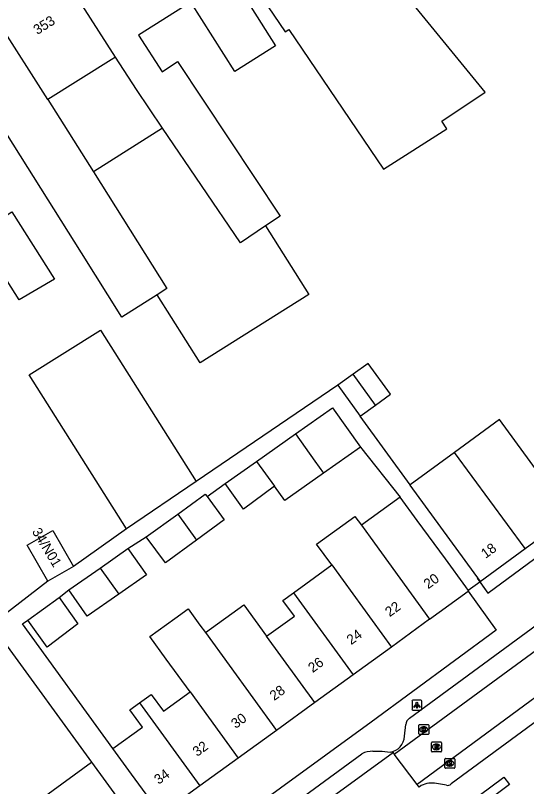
# Model space of a CAD drawing. Extents: x 159822 to 160765, y 380693 to 381634.
# Drawn here: x 160009.6 to 160061, y 381446.3 to 381523.9 of the extents above; entities that cross this region are included whole.
import ezdxf

# ---------------------------------------------------------------- set-up
doc = ezdxf.new("R2010")
doc.units = 0
for name, color, linetype in [('IMGEO_Kolk', 7, 'Continuous'), ('IMGEO_Lichtpunt', 7, 'Continuous'), ('IMGEO_Muur', 7, 'Continuous'), ('IMGEO_Pand', 7, 'Continuous'), ('IMGEO_Pand_nummerreeks', 7, 'Continuous'), ('IMGEO_Parkeervlak_open', 7, 'Continuous'), ('IMGEO_Rijbaan_lokaal_open', 7, 'Continuous'), ('IMGEO_Rioolput', 7, 'Continuous'), ('IMGEO_Voetpad_open', 7, 'Continuous')]:
    doc.layers.add(name, color=color, linetype=linetype)

msp = doc.modelspace()

# ---------------------------------------------------------------- linework, layer by layer
at = {"layer": 'IMGEO_Kolk'}
for p, q in [((160050.192, 381451.574), (160050.192, 381452.426)), ((160050.267, 381452.5), (160051.119, 381452.5)), ((160050.68, 381452.28), (160050.705, 381452.28)), ((160051.193, 381452.426), (160051.193, 381451.574)), ((160051.119, 381451.5), (160050.267, 381451.5)), ((160050.703, 381451.72), (160050.678, 381451.72)), ((160052.803, 381448.172), (160052.803, 381449.024)), ((160052.878, 381449.098), (160053.73, 381449.098)), ((160053.804, 381449.024), (160053.804, 381448.172)), ((160053.314, 381448.318), (160053.289, 381448.318)), ((160053.291, 381448.878), (160053.316, 381448.878)), ((160053.73, 381448.098), (160052.878, 381448.098))]:
    msp.add_line(p, q, dxfattribs=at)
for points in [[(160050.192, 381451.574), (160050.192, 381452.426)], [(160050.267, 381452.5), (160051.119, 381452.5)], [(160050.513, 381452.2), (160050.636, 381452.2), (160050.636, 381452.049), (160050.766, 381452.2), (160050.93, 381452.2), (160050.784, 381452.049), (160050.937, 381451.8), (160050.785, 381451.8), (160050.7, 381451.964), (160050.636, 381451.897), (160050.636, 381451.8), (160050.513, 381451.8), (160050.513, 381452.2)], [(160051.193, 381452.426), (160051.193, 381451.574)], [(160051.119, 381451.5), (160050.267, 381451.5)], [(160052.803, 381448.172), (160052.803, 381449.024)], [(160052.878, 381449.098), (160053.73, 381449.098)], [(160053.804, 381449.024), (160053.804, 381448.172)], [(160053.124, 381448.798), (160053.247, 381448.798), (160053.247, 381448.647), (160053.377, 381448.798), (160053.541, 381448.798), (160053.395, 381448.647), (160053.548, 381448.398), (160053.396, 381448.398), (160053.311, 381448.562), (160053.247, 381448.495), (160053.247, 381448.398), (160053.124, 381448.398), (160053.124, 381448.798)], [(160053.73, 381448.098), (160052.878, 381448.098)]]:
    msp.add_lwpolyline(points, dxfattribs=at)
for centre, start, end in [((160050.269, 381452.424), 91.55205, 178.44795), ((160050.269, 381452.424), 91.55205, 178.44795), ((160051.117, 381452.424), 1.55205, 88.44795), ((160051.117, 381452.424), 1.55205, 88.44795), ((160050.269, 381451.576), 181.55205, 268.44795), ((160050.269, 381451.576), 181.55205, 268.44795), ((160051.117, 381451.576), 271.55205, 358.44795), ((160051.117, 381451.576), 271.55205, 358.44795), ((160052.88, 381449.022), 91.55205, 178.44795), ((160052.88, 381449.022), 91.55205, 178.44795), ((160053.728, 381449.022), 1.55205, 88.44795), ((160053.728, 381449.022), 1.55205, 88.44795), ((160052.88, 381448.174), 181.55205, 268.44795), ((160052.88, 381448.174), 181.55205, 268.44795), ((160053.728, 381448.174), 271.55205, 358.44795), ((160053.728, 381448.174), 271.55205, 358.44795)]:
    msp.add_arc(centre, 0.0765, start, end, dxfattribs=at)
for centre, major_axis, ratio, start_param, end_param in [((160050.679, 381452), (-0.387, 0.002), 0.722429, 4.712389, 7.853982), ((160050.704, 381452), (-0.39, 0.002), 0.717154, 1.570796, 4.712389), ((160053.29, 381448.598), (-0.387, 0.002), 0.722429, 4.712389, 7.853982), ((160053.315, 381448.598), (-0.39, 0.002), 0.717154, 1.570796, 4.712389)]:
    msp.add_ellipse(centre, major_axis=major_axis, ratio=ratio, start_param=start_param, end_param=end_param, dxfattribs=at)
at = {"layer": 'IMGEO_Lichtpunt'}
for p, q in [((160049.506, 381454.857), (160049.506, 381454.05)), ((160049.506, 381454.857), (160049.506, 381454.05)), ((160050.408, 381454.952), (160049.6, 381454.952)), ((160050.408, 381454.952), (160049.6, 381454.952)), ((160050.502, 381454.05), (160050.502, 381454.857)), ((160050.502, 381454.05), (160050.502, 381454.857)), ((160049.6, 381453.956), (160050.408, 381453.956)), ((160049.6, 381453.956), (160050.408, 381453.956))]:
    msp.add_line(p, q, dxfattribs=at)
for points in [[(160049.88, 381454.521), (160049.919, 381454.493), (160049.731, 381454.231), (160049.693, 381454.258), (160049.88, 381454.521)], [(160049.982, 381454.473), (160050.029, 381454.473), (160050.029, 381454.151), (160049.982, 381454.151), (160049.982, 381454.473)], [(160050.092, 381454.493), (160050.13, 381454.52), (160050.317, 381454.258), (160050.278, 381454.23), (160050.092, 381454.493)]]:
    msp.add_lwpolyline(points, dxfattribs=at)
msp.add_circle((160050.005, 381454.655), 0.0994, dxfattribs=at)
for centre, start, end in [((160049.6, 381454.857), 90, 180), ((160049.6, 381454.857), 90, 180), ((160050.408, 381454.857), 0, 90), ((160050.408, 381454.857), 0, 90), ((160049.6, 381454.05), 180, 270), ((160049.6, 381454.05), 180, 270), ((160050.408, 381454.05), 270, 0), ((160050.408, 381454.05), 270, 360)]:
    msp.add_arc(centre, 0.0946, start, end, dxfattribs=at)
at = {"layer": 'IMGEO_Muur'}
msp.add_lwpolyline([(160056.063, 381467.236), (160057.143, 381465.734), (160069.783, 381475.059)], dxfattribs=at)
at = {"layer": 'IMGEO_Pand'}
for points in [[(160028.91, 381533.878), (160031.703, 381529.731), (160036.757, 381522.228), (160037.103, 381522.461), (160046.627, 381508.396), (160053.016, 381512.481), (160052.51, 381513.232), (160056.874, 381516.17), (160044.202, 381531.699), (160041.112, 381535.824), (160038.115, 381539.825)], [(160027.93, 381533.3), (160029.382, 381530.994), (160035.788, 381520.822), (160031.683, 381518.237), (160027.275, 381525.235), (160021.998, 381521.911), (160024.38, 381518.196), (160025.929, 381519.252), (160036.236, 381503.697), (160034.773, 381502.7)], [(160019.688, 381519.696), (160014.641, 381527.565)], [(160012.891, 381515.416), (160007.851, 381523.273)], [(160023.877, 381495.766), (160020.325, 381493.529), (160016.251, 381500), (160008.062, 381513.006), (160006.05, 381516.226), (160003.39, 381520.454)], [(160019.688, 381519.696), (160019.25, 381519.42), (160012.891, 381515.416)], [(160024.413, 381512.525), (160021.789, 381516.419), (160019.688, 381519.696)], [(160012.891, 381515.416), (160017.462, 381508.151)], [(160024.413, 381512.525), (160017.462, 381508.151)], [(160034.773, 381502.7), (160032.263, 381500.989), (160024.413, 381512.525)], [(160017.462, 381508.151), (160024.864, 381496.387), (160023.877, 381495.766)], [(160010.01, 381495.246), (160005.773, 381501.901), (160009.243, 381504.11), (160013.556, 381497.336), (160010.01, 381495.246)], [(160034.773, 381502.7), (160039.123, 381495.791), (160028.194, 381488.91), (160023.877, 381495.766)], [(160020.806, 381472.199), (160011.015, 381487.705), (160018.16, 381492.216), (160027.791, 381476.962)], [(160045.827, 381484.663), (160047.35, 381485.764), (160045.11, 381488.863), (160043.586, 381487.762)], [(160043.586, 381487.762), (160042.062, 381486.661)], [(160045.827, 381484.663), (160043.586, 381487.762)], [(160042.062, 381486.661), (160044.303, 381483.561)], [(160044.303, 381483.561), (160045.827, 381484.663)], [(160037.79, 381481.77), (160041.5, 381484.395), (160044.316, 381480.415)], [(160060.872, 381470.222), (160065.379, 381473.526), (160058.321, 381483.22), (160053.782, 381479.891)], [(160033.862, 381478.99), (160037.79, 381481.77)], [(160037.79, 381481.77), (160039.728, 381479.014), (160040.613, 381477.795)], [(160044.316, 381480.415), (160040.613, 381477.795)], [(160053.782, 381479.891), (160049.318, 381476.617)], [(160060.872, 381470.222), (160053.782, 381479.891)], [(160030.724, 381476.771), (160033.862, 381478.99)], [(160033.862, 381478.99), (160035.681, 381476.485)], [(160040.613, 381477.795), (160036.727, 381475.046), (160035.681, 381476.485)], [(160027.791, 381476.962), (160020.806, 381472.199)], [(160035.681, 381476.485), (160032.554, 381474.178), (160030.724, 381476.771)], [(160049.318, 381476.617), (160049.275, 381476.586), (160056.365, 381466.917)], [(160025.944, 381473.692), (160028.719, 381475.708), (160028.906, 381475.45)], [(160028.906, 381475.45), (160030.619, 381473.093), (160027.843, 381471.076)], [(160048.331, 381475.376), (160044.417, 381472.558)], [(160055.163, 381466.036), (160054.92, 381466.37), (160052.87, 381469.192), (160050.028, 381473.047), (160048.331, 381475.376)], [(160022.772, 381471.387), (160025.944, 381473.692)], [(160025.944, 381473.692), (160027.843, 381471.076)], [(160041.436, 381468.563), (160039.91, 381470.664), (160043.761, 381473.461), (160044.417, 381472.558)], [(160044.417, 381472.558), (160045.288, 381471.358), (160051.282, 381463.103)], [(160012.867, 381466.922), (160010.789, 381470.552), (160013.392, 381472.043), (160015.47, 381468.413)], [(160027.843, 381471.076), (160024.703, 381468.795), (160022.772, 381471.387)], [(160018.128, 381468.252), (160020.936, 381470.22), (160020.937, 381470.219)], [(160020.937, 381470.219), (160022.792, 381467.571), (160020.029, 381465.635)], [(160056.365, 381466.917), (160060.872, 381470.222)], [(160015.47, 381468.413), (160012.867, 381466.922)], [(160037.583, 381465.767), (160038.82, 381466.665), (160041.436, 381468.563)], [(160041.436, 381468.563), (160042.569, 381467.002), (160047.431, 381460.307)], [(160014.989, 381466.052), (160018.128, 381468.252)], [(160018.128, 381468.252), (160020.029, 381465.635)], [(160020.029, 381465.635), (160016.845, 381463.403), (160014.989, 381466.052)], [(160055.158, 381465.918), (160055.217, 381465.961), (160055.163, 381466.036)], [(160010.869, 381463.024), (160014.032, 381465.274)], [(160014.032, 381465.274), (160015.913, 381462.631), (160012.812, 381460.293), (160010.869, 381463.024)], [(160034.884, 381461.383), (160037.681, 381463.415), (160036.528, 381465.001), (160037.583, 381465.767)], [(160037.583, 381465.767), (160043.58, 381457.509)], [(160051.282, 381463.103), (160055.158, 381465.918)], [(160028.73, 381461.756), (160032.582, 381464.553), (160034.884, 381461.383)], [(160027.183, 381455.784), (160024.788, 381459.082), (160023.133, 381461.362), (160025.638, 381463.181), (160026.985, 381464.159), (160028.179, 381462.515), (160028.73, 381461.756)], [(160051.282, 381463.103), (160047.431, 381460.307)], [(160028.73, 381461.756), (160035.876, 381451.915)], [(160039.728, 381454.712), (160034.884, 381461.383)], [(160047.431, 381460.307), (160043.58, 381457.509)], [(160043.58, 381457.509), (160039.728, 381454.712)], [(160022.109, 381454.67), (160023.279, 381455.52), (160024.501, 381453.837), (160027.183, 381455.784)], [(160027.183, 381455.784), (160032.025, 381449.117)], [(160019.421, 381450.096), (160022.385, 381452.249), (160021.138, 381453.965), (160022.109, 381454.67)], [(160022.109, 381454.67), (160028.173, 381446.32)], [(160039.728, 381454.712), (160035.876, 381451.915)], [(160035.876, 381451.915), (160032.025, 381449.117)], [(160024.239, 381443.463), (160021.3, 381447.509), (160019.421, 381450.096)], [(160032.025, 381449.117), (160028.173, 381446.32)], [(160012.548, 381445.248), (160017.286, 381448.698)], [(160017.286, 381448.698), (160018.715, 381446.73), (160021.653, 381442.684)], [(160028.173, 381446.32), (160024.239, 381443.463)]]:
    msp.add_lwpolyline(points, dxfattribs=at)
at = {"layer": 'IMGEO_Parkeervlak_open'}
msp.add_lwpolyline([(160047.631, 381449.677), (160047.299, 381449.724)], dxfattribs=at)
at = {"layer": 'IMGEO_Rijbaan_lokaal_open'}
for points in [[(160047.723, 381449.532), (160071.444, 381466.944)], [(160073.316, 381463.635), (160050.029, 381446.475)], [(160047.631, 381449.677), (160029.153, 381436.195)], [(160047.723, 381449.532), (160047.631, 381449.677)], [(160050.029, 381446.475), (160047.723, 381449.532)], [(160050.226, 381446.2), (160050.029, 381446.475)]]:
    msp.add_lwpolyline(points, dxfattribs=at)
at = {"layer": 'IMGEO_Rioolput'}
for p, q in [((160051.465, 381449.82), (160051.465, 381450.672)), ((160051.54, 381450.746), (160052.392, 381450.746)), ((160051.953, 381450.526), (160051.978, 381450.526)), ((160052.466, 381450.672), (160052.466, 381449.82)), ((160052.392, 381449.746), (160051.54, 381449.746)), ((160051.976, 381449.966), (160051.951, 381449.966))]:
    msp.add_line(p, q, dxfattribs=at)
for points in [[(160051.465, 381449.82), (160051.465, 381450.672)], [(160051.54, 381450.746), (160052.392, 381450.746)], [(160052.466, 381450.672), (160052.466, 381449.82)], [(160052.392, 381449.746), (160051.54, 381449.746)], [(160052.054, 381450.444), (160051.802, 381450.446), (160051.802, 381450.046)], [(160051.802, 381450.046), (160051.926, 381450.046), (160051.926, 381450.208), (160051.937, 381450.208)], [(160051.98, 381450.365), (160051.926, 381450.365), (160051.926, 381450.284)], [(160051.926, 381450.284), (160051.978, 381450.284)], [(160051.984, 381450.179), (160052.055, 381450.046), (160052.195, 381450.046), (160052.13, 381450.172)]]:
    msp.add_lwpolyline(points, dxfattribs=at)
for centre, radius, start, end in [((160051.542, 381450.67), 0.0765, 91.55205, 178.44795), ((160051.542, 381450.67), 0.0765, 91.55205, 178.44795), ((160052.39, 381450.67), 0.0765, 1.55205, 88.44795), ((160052.39, 381450.67), 0.0765, 1.55205, 88.44795), ((160051.542, 381449.822), 0.0765, 181.55205, 268.44795), ((160051.542, 381449.822), 0.0765, 181.55205, 268.44795), ((160051.936, 381450.155), 0.0533, 26.02933, 88.69889), ((160051.962, 381450.473), 0.19, 274.7715, 282.96867), ((160051.986, 381450.269), 0.0964, 77.00612, 93.18647), ((160052, 381450.326), 0.0378, 276.66336, 79.67722), ((160052.053, 381450.334), 0.109, 350.36119, 89.41601), ((160052.051, 381450.334), 0.112, 277.58423, 350.98172), ((160052.035, 381450.119), 0.108, 29.51342, 73.79051), ((160052.39, 381449.822), 0.0765, 271.55205, 358.44795), ((160052.39, 381449.822), 0.0765, 271.55205, 358.44795)]:
    msp.add_arc(centre, radius, start, end, dxfattribs=at)
for centre, major_axis, ratio, start_param, end_param in [((160051.952, 381450.246), (-0.387, 0.002), 0.722429, 4.712389, 7.853982), ((160051.977, 381450.246), (-0.39, 0.002), 0.717154, 1.570796, 4.712389)]:
    msp.add_ellipse(centre, major_axis=major_axis, ratio=ratio, start_param=start_param, end_param=end_param, dxfattribs=at)
at = {"layer": 'IMGEO_Voetpad_open'}
for points in [[(160042.062, 381486.661), (160042.046, 381486.683), (160027.791, 381476.962)], [(160049.318, 381476.617), (160044.303, 381483.561)], [(160044.316, 381480.415), (160048.331, 381475.376)], [(160056.317, 381466.882), (160057.143, 381465.734), (160069.783, 381475.059), (160072.309, 381476.925), (160076.618, 381473.531), (160081.375, 381469.783), (160081.79, 381469.456), (160091.085, 381462.133), (160111.187, 381476.867)], [(160028.906, 381475.45), (160030.724, 381476.771)], [(160020.806, 381472.199), (160015.47, 381468.413)], [(160020.937, 381470.219), (160022.772, 381471.387)], [(160012.867, 381466.922), (160007.209, 381462.575), (160008.252, 381461.14), (160017.286, 381448.698)], [(160055.163, 381466.036), (160056.317, 381466.882)], [(160056.317, 381466.882), (160056.365, 381466.917)], [(160014.032, 381465.274), (160014.989, 381466.052)], [(160049.257, 381453.137), (160067.431, 381466.507)], [(160055.158, 381465.918), (160057.967, 381461.996), (160045.402, 381452.747), (160027.173, 381439.443)], [(160019.421, 381450.096), (160010.316, 381462.631), (160010.869, 381463.024)], [(160072.031, 381460.205), (160053.453, 381446.521)], [(160048.768, 381451.325), (160048.872, 381452.494)], [(160045.582, 381449.804), (160046.502, 381449.825), (160047.299, 381449.724)], [(160030.306, 381439.198), (160044.452, 381449.564)], [(160059.311, 381446.468), (160055.654, 381443.725), (160055.087, 381444.493), (160058.736, 381447.208), (160059.311, 381446.468)], [(160050.44, 381446.355), (160050.226, 381446.2)], [(160052.965, 381446.381), (160051.973, 381446.551)]]:
    msp.add_lwpolyline(points, dxfattribs=at)
for centre, radius, start, end in [((160049.761, 381452.399), 0.894, 124.30893, 173.86845), ((160047.062, 381451.416), 1.708, 277.96916, 356.95487), ((160045.455, 381447.621), 2.187, 86.67445, 117.30722), ((160051.458, 381444.485), 2.129, 76.00441, 118.5675), ((160053.073, 381446.926), 0.555, 258.81195, 313.20285)]:
    msp.add_arc(centre, radius, start, end, dxfattribs=at)

# ---------------------------------------------------------------- texts
at = {"layer": 'IMGEO_Pand_nummerreeks'}
for s, rotation, p in [('353', 32.44147, (160011.823, 381521.906)), ('34/N01', 301.02954, (160011.249, 381471.937)), ('18', 36.25104, (160056.903, 381469.171)), ('20', 35.98748, (160051.134, 381466.11)), ('22', 35.98748, (160047.257, 381463.294)), ('24', 35.9893, (160043.387, 381460.484)), ('26', 35.9893, (160039.515, 381457.672)), ('28', 35.98748, (160035.645, 381454.861)), ('30', 35.98748, (160031.772, 381452.049)), ('32', 35.9893, (160027.896, 381449.233)), ('34', 35.9893, (160024.026, 381446.423))]:
    msp.add_text(s, height=1, rotation=rotation, dxfattribs=at).set_placement(p)

doc.saveas('drawing.dxf')
